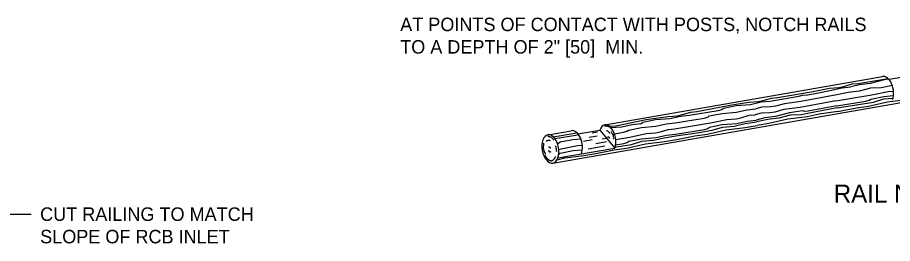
# Model space of a CAD drawing. Extents: x 49991 to 50288, y 49919 to 50011.
# Drawn here: x 50008.695 to 50012.585, y 49991.075 to 49992.081 of the extents above; entities that cross this region are included whole.
import ezdxf

# ---------------------------------------------------------------- set-up
doc = ezdxf.new("R2010")
doc.units = 0
for name, color, linetype in [('Level 1', 7, 'Continuous'), ('Level 2', 7, 'Continuous'), ('Level 3', 7, 'Continuous')]:
    doc.layers.add(name, color=color, linetype=linetype)

msp = doc.modelspace()

# ---------------------------------------------------------------- linework, layer by layer
at = {"layer": 'Level 1'}
for p, q in [((50011.07515827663, 49991.43285974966), (50014.2479885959, 49991.986852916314)), ((50011.30581186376, 49991.60257983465), (50012.54099410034, 49991.818363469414)), ((50012.66717761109, 49991.82165266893), (50012.56974109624, 49991.80464055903)), ((50011.053831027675, 49991.55884996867), (50011.15668103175, 49991.57681846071)), ((50011.18651081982, 49991.562982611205), (50011.283456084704, 49991.5799187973)), ((50011.23718243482, 49991.548498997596), (50011.27211621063, 49991.55462696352)), ((50011.24964567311, 49991.56810730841), (50011.273417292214, 49991.57229858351)), ((50011.283456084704, 49991.5799187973), (50011.35046357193, 49991.49992771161)), ((50011.21075119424, 49991.53070873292), (50011.24926361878, 49991.537436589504)), ((50011.26666973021, 49991.52050762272), (50011.31321730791, 49991.52864027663)), ((50011.29437823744, 49991.54051945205), (50011.313618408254, 49991.543912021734)), ((50011.09761781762, 49991.45575595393), (50011.35046357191, 49991.49992771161)), ((50011.2327173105, 49991.4963478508), (50011.305634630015, 49991.509151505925))]:
    msp.add_line(p, q, dxfattribs=at)
for points in [[(50012.07324422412, 49991.72466370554), (50012.23268566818, 49991.75096155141), (50012.30517618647, 49991.766056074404), (50012.346365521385, 49991.76918793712), (50012.36822040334, 49991.773762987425), (50012.40525061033, 49991.78517681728), (50012.431932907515, 49991.78725309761)], [(50012.567762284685, 49991.80683238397), (50012.547524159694, 49991.803948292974), (50012.485090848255, 49991.78719284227), (50012.438105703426, 49991.781454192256), (50012.39918382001, 49991.77178213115)], [(50012.431932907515, 49991.78725309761), (50012.565337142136, 49991.80928998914)], [(50012.040441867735, 49991.709103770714), (50012.16913199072, 49991.730356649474), (50012.18463403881, 49991.73466474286), (50012.208500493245, 49991.7364012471), (50012.24928202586, 49991.74384660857), (50012.313071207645, 49991.75714233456), (50012.35922247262, 49991.76767329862), (50012.39918382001, 49991.77178213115)], [(50012.33357019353, 49991.710384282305), (50012.493007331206, 49991.73672338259), (50012.56559667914, 49991.75186992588), (50012.58947367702, 49991.75365337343)], [(50012.584284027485, 49991.77780037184), (50012.53496525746, 49991.768648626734), (50012.48659007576, 49991.76603863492), (50012.43616170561, 49991.752934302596), (50012.38743401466, 49991.74690949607), (50012.336721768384, 49991.736924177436)], [(50011.6816977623, 49991.646446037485), (50011.81040635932, 49991.66772169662), (50011.82591056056, 49991.67200916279), (50011.83314928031, 49991.6773730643), (50011.88988445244, 49991.68898798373), (50011.95435203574, 49991.69444550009), (50012.00054455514, 49991.70498077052), (50012.040441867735, 49991.709103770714)], [(50011.71450442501, 49991.66196471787), (50011.86181156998, 49991.690905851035), (50011.94651243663, 49991.703427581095), (50011.987662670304, 49991.70653451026), (50012.00953602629, 49991.71113234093), (50012.0464815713, 49991.72255818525), (50012.07324422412, 49991.72466370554)], [(50012.33357019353, 49991.710384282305), (50012.17461243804, 49991.68105083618), (50012.101166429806, 49991.67071508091), (50012.06148892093, 49991.659692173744), (50012.0393260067, 49991.656669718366), (50012.00073117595, 49991.6548512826), (50011.97489442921, 49991.64767112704)], [(50012.336721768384, 49991.736924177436), (50012.17778033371, 49991.707634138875), (50012.10429522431, 49991.69727345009), (50012.06464049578, 49991.686232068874), (50012.042496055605, 49991.68323239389), (50012.003845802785, 49991.68134561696), (50011.978018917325, 49991.67427075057)], [(50012.3376315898, 49991.68705784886), (50012.46628907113, 49991.70822391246), (50012.48179111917, 49991.71253200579), (50012.48902553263, 49991.71793716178), (50012.54582043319, 49991.72957916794), (50012.58948304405, 49991.73328844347)], [(50012.33896423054, 49991.67908554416), (50012.43353296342, 49991.69341947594), (50012.500426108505, 49991.70440573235), (50012.54688647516, 49991.71836783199), (50012.58754041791, 49991.72210379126)], [(50012.34176188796, 49991.663071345), (50012.42418304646, 49991.67951526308), (50012.478014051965, 49991.686990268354), (50012.56265424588, 49991.706147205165), (50012.647767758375, 49991.71657487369), (50012.70037792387, 49991.72575741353)], [(50011.61930405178, 49991.61153266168), (50011.74794646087, 49991.63284311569), (50011.76351685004, 49991.63709578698), (50011.77068722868, 49991.642515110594), (50011.827509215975, 49991.65409738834), (50011.891935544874, 49991.65955059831), (50011.938105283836, 49991.670104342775), (50011.978018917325, 49991.67427075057)], [(50012.3376315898, 49991.68705784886), (50012.209385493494, 49991.66334908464), (50012.19330863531, 49991.66215048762), (50012.18475359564, 49991.66480229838), (50012.12734172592, 49991.65647390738), (50012.0649290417, 49991.639720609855), (50012.017900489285, 49991.633998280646), (50011.978994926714, 49991.62436962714)], [(50012.33896423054, 49991.67908554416), (50012.245267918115, 49991.66058888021), (50012.17860585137, 49991.648187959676), (50012.130189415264, 49991.64557366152), (50012.079806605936, 49991.63243238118), (50012.031010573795, 49991.626462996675), (50011.98036666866, 49991.616422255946)], [(50011.355760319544, 49991.599306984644), (50011.490507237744, 49991.62758437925), (50011.58777263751, 49991.64072859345), (50011.628959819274, 49991.64388108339), (50011.65078976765, 49991.64849523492), (50011.6877645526, 49991.659840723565), (50011.71450442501, 49991.66196471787)], [(50011.46328139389, 49991.60821606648), (50011.467251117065, 49991.60933941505), (50011.47446920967, 49991.61470116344), (50011.53118590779, 49991.62629330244), (50011.59561008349, 49991.631767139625), (50011.641818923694, 49991.64234581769), (50011.6816977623, 49991.646446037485)], [(50011.6162904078, 49991.58506972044), (50011.775649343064, 49991.61135895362), (50011.84823653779, 49991.62652612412), (50011.889361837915, 49991.62967215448), (50011.911257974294, 49991.63425151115), (50011.94820782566, 49991.64563610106), (50011.97489442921, 49991.64767112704)], [(50012.34176188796, 49991.663071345), (50012.25873306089, 49991.65065097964), (50012.20546756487, 49991.63935654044), (50012.11943444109, 49991.62874946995), (50012.035786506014, 49991.60967525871), (50011.98313723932, 49991.60046778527)], [(50011.32665228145, 49991.59649789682), (50011.329036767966, 49991.59722639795), (50011.355760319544, 49991.599306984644)], [(50011.333060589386, 49991.59064016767), (50011.38114065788, 49991.59467899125), (50011.42732456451, 49991.6052967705), (50011.467251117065, 49991.60933941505)], [(50011.34866228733, 49991.56343049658), (50011.38920666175, 49991.57014412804), (50011.404713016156, 49991.574410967), (50011.411970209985, 49991.57979764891), (50011.46874233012, 49991.5914581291), (50011.53316650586, 49991.596931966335), (50011.579363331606, 49991.60742598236), (50011.61930405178, 49991.61153266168)], [(50011.62033763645, 49991.56167925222), (50011.748912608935, 49991.58283670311), (50011.76448424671, 49991.58727717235), (50011.77161121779, 49991.59271281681), (50011.82841257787, 49991.6042929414), (50011.89284751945, 49991.60966364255), (50011.939081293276, 49991.62020321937), (50011.978994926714, 49991.62436962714)], [(50011.62168013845, 49991.55381223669), (50011.71610232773, 49991.568151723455), (50011.78307888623, 49991.57893816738), (50011.829551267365, 49991.59298492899), (50011.88131964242, 49991.59784664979), (50011.92931874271, 49991.60865390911), (50011.98036666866, 49991.616422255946)], [(50011.62443654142, 49991.537793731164), (50011.70677949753, 49991.5541877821), (50011.760742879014, 49991.56159319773), (50011.84533320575, 49991.580828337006), (50011.930508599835, 49991.591262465), (50011.98313723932, 49991.60046778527)], [(50011.07650606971, 49991.55050795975), (50011.1818807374, 49991.567896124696)], [(50011.08429500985, 49991.5419259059), (50011.1779538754, 49991.55737301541), (50011.18905234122, 49991.55972009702)], [(50011.351942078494, 49991.5045846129), (50011.35751122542, 49991.50542655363), (50011.42445208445, 49991.51635523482), (50011.470905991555, 49991.530379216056), (50011.522658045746, 49991.535197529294), (50011.57063867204, 49991.54598200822), (50011.62168013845, 49991.55381223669)], [(50011.35394634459, 49991.514278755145), (50011.39030428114, 49991.52027655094), (50011.40576292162, 49991.524600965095), (50011.41302442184, 49991.52994639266), (50011.46976174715, 49991.54154068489), (50011.53420224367, 49991.54705792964), (50011.580378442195, 49991.55754979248), (50011.62033763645, 49991.56167925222)], [(50011.35432657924, 49991.53833214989), (50011.41698559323, 49991.548730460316), (50011.4896118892, 49991.56392256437), (50011.53072948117, 49991.566942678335), (50011.55261269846, 49991.571645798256), (50011.589569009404, 49991.58296850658), (50011.6162904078, 49991.58506972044)], [(50011.09570934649, 49991.52015532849), (50011.10009781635, 49991.521366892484), (50011.10728882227, 49991.52678836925), (50011.16408587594, 49991.5384097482), (50011.19899842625, 49991.541345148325)], [(50011.26580973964, 49991.47521079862), (50011.3481656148, 49991.49148108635), (50011.402128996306, 49991.498886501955), (50011.48668577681, 49991.51824325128), (50011.57178512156, 49991.52860688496), (50011.62443654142, 49991.537793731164)], [(50011.10139390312, 49991.47179684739), (50011.108369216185, 49991.47708580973), (50011.16521183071, 49991.488670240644), (50011.20605815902, 49991.49212602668)], [(50011.10159282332, 49991.49403532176), (50011.11231621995, 49991.49580584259), (50011.1849098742, 49991.51091113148), (50011.20598928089, 49991.512527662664)], [(50011.093971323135, 49991.44781453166), (50011.128046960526, 49991.45557565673), (50011.21326576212, 49991.46599346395), (50011.26580973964, 49991.47521079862)]]:
    msp.add_lwpolyline(points, dxfattribs=at)
for centre, start_param, end_param in [((50012.552010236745, 49991.75545298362), 3.925707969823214, 6.306125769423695), ((50011.316874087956, 49991.53968844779), 3.9315222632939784, 7.063530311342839), ((50011.06413370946, 49991.49580670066), 3.9256121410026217, 7.063370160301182), ((50011.16856108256, 49991.51405562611), 3.9254893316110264, 6.306125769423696), ((50011.06412712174, 49991.49578870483), 0.7858875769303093, 3.9259797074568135)]:
    msp.add_ellipse(centre, major_axis=(-0.011049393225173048, 0.06292576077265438), ratio=0.5774931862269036, start_param=start_param, end_param=end_param, dxfattribs=at)
for points in [[(50011.32489066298, 49991.5929985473), (50011.322799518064, 49991.59505312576), (50011.31675475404, 49991.59702863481), (50011.313380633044, 49991.59799009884), (50011.309090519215, 49991.597938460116), (50011.305137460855, 49991.597254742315)], [(50011.31377223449, 49991.57765860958), (50011.314900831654, 49991.57723426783), (50011.31970671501, 49991.57494176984), (50011.32303967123, 49991.57157803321), (50011.32590840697, 49991.56866628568), (50011.32681256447, 49991.564798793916)], [(50011.34604103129, 49991.53880178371), (50011.34596407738, 49991.538939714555), (50011.34562925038, 49991.54714128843), (50011.3448470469, 49991.55143854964), (50011.344066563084, 49991.557716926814), (50011.33845944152, 49991.56488855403), (50011.33580188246, 49991.57097099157), (50011.33429204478, 49991.573649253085)], [(50011.03399555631, 49991.52136682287), (50011.033950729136, 49991.5190242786), (50011.03391480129, 49991.51785542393), (50011.033815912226, 49991.51669158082), (50011.0333444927, 49991.51308200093), (50011.0328380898, 49991.509478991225), (50011.032522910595, 49991.507906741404), (50011.03212706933, 49991.50634376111), (50011.03179227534, 49991.50477461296), (50011.03169205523, 49991.50398290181), (50011.03166648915, 49991.50358441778), (50011.03166023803, 49991.50318385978), (50011.031832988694, 49991.50175771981), (50011.03222079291, 49991.50036278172), (50011.0326728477, 49991.49897556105), (50011.0328758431, 49991.49827750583), (50011.03303834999, 49991.49757257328), (50011.03351549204, 49991.49497398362), (50011.03399780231, 49991.49237632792), (50011.0348418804, 49991.48835394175), (50011.035344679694, 49991.48635999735), (50011.035628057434, 49991.485369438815), (50011.03593724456, 49991.484383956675), (50011.03707273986, 49991.481789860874), (50011.03856534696, 49991.479382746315), (50011.04301372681, 49991.472924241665)], [(50011.04474557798, 49991.53024868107), (50011.045729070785, 49991.53094620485), (50011.050319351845, 49991.53364460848), (50011.05497253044, 49991.5345228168), (50011.05899129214, 49991.53526945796), (50011.06270198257, 49991.53385320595)], [(50011.0534452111, 49991.552552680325), (50011.057203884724, 49991.55190243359), (50011.06195662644, 49991.55091806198), (50011.06468269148, 49991.54997235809), (50011.067729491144, 49991.548351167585), (50011.06977076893, 49991.54637479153), (50011.071798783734, 49991.54412595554), (50011.07490337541, 49991.54155160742), (50011.07590231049, 49991.54057157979), (50011.07727275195, 49991.53862943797), (50011.0786274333, 49991.53603924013), (50011.078957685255, 49991.535072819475)], [(50011.318616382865, 49991.549610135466), (50011.31881062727, 49991.54977805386), (50011.31891154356, 49991.54986121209), (50011.31896301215, 49991.549902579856), (50011.31901517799, 49991.54994380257), (50011.31917018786, 49991.55005168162), (50011.31933120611, 49991.55013858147), (50011.31966833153, 49991.550255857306), (50011.32038238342, 49991.55030920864), (50011.32111035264, 49991.55020647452), (50011.321464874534, 49991.55012864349), (50011.32180525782, 49991.5500502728), (50011.32203356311, 49991.54999658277), (50011.32226045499, 49991.54993603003), (50011.32270750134, 49991.54978124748), (50011.323141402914, 49991.549559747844), (50011.32335186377, 49991.549415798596), (50011.323455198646, 49991.549334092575), (50011.32355716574, 49991.549245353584), (50011.323817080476, 49991.54899474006), (50011.324052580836, 49991.5487374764), (50011.324441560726, 49991.54819890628), (50011.32470655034, 49991.54762145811), (50011.324787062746, 49991.54731559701), (50011.32482999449, 49991.546996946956), (50011.32487013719, 49991.546242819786), (50011.32488388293, 49991.5454921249), (50011.324874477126, 49991.54474303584), (50011.32484516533, 49991.54399372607), (50011.32482312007, 49991.543536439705), (50011.32480140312, 49991.54307919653), (50011.324776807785, 49991.542622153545), (50011.32474612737, 49991.542165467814)], [(50011.05707632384, 49991.50441172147), (50011.0571061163, 49991.504435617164), (50011.057158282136, 49991.5044768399), (50011.057313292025, 49991.50458471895), (50011.057474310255, 49991.5046716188), (50011.057811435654, 49991.50478889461), (50011.05798632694, 49991.50482244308), (50011.0581641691, 49991.504843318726), (50011.05852548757, 49991.50484224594), (50011.05871047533, 49991.50482421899), (50011.058892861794, 49991.50480205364), (50011.05907355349, 49991.50477430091), (50011.059253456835, 49991.50473951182), (50011.05960797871, 49991.50466168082), (50011.059948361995, 49991.50458331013), (50011.06017666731, 49991.5045296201), (50011.06040355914, 49991.50446906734), (50011.06085060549, 49991.50431428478), (50011.061284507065, 49991.50409278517), (50011.061494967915, 49991.5039488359), (50011.0615983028, 49991.503867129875), (50011.06170026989, 49991.503778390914), (50011.06196018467, 49991.503527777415), (50011.06219568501, 49991.50327051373), (50011.062401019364, 49991.503010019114), (50011.062495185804, 49991.502873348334), (50011.06258466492, 49991.50273194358), (50011.06273337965, 49991.50245019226), (50011.06284965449, 49991.50215449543), (50011.06293016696, 49991.50184863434), (50011.06297309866, 49991.50152998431), (50011.063013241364, 49991.500775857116), (50011.0630269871, 49991.500025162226), (50011.06301758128, 49991.49927607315), (50011.06298826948, 49991.4985267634), (50011.06296622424, 49991.498069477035), (50011.06294450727, 49991.497612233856), (50011.062932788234, 49991.49738376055)], [(50011.06588441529, 49991.48338071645), (50011.06575481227, 49991.48315906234), (50011.06568616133, 49991.48304776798), (50011.06565081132, 49991.482991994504), (50011.06561475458, 49991.48293613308), (50011.06550289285, 49991.48278397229), (50011.065378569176, 49991.48264972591), (50011.065097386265, 49991.4824298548), (50011.06443883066, 49991.48214874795), (50011.06371669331, 49991.482010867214), (50011.06335603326, 49991.48197002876), (50011.06300857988, 49991.48193426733), (50011.06277516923, 49991.48191134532), (50011.062540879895, 49991.48189537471), (50011.062067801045, 49991.4818974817), (50011.06158561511, 49991.481966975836), (50011.061339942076, 49991.4820352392), (50011.06121575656, 49991.48207919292), (50011.06109059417, 49991.48213024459), (50011.06076366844, 49991.482283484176), (50011.06045770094, 49991.48245090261), (50011.059915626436, 49991.48283498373), (50011.059478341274, 49991.483295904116), (50011.05930336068, 49991.48355937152), (50011.05915981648, 49991.48384707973), (50011.058878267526, 49991.48454782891), (50011.05862280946, 49991.48525385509), (50011.05838978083, 49991.48596583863), (50011.058175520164, 49991.486684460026), (50011.05804869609, 49991.487124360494), (50011.05792157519, 49991.4875641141), (50011.05779724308, 49991.48800460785), (50011.057678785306, 49991.488446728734)], [(50011.091779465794, 49991.48475852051), (50011.0920931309, 49991.48762025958), (50011.09139070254, 49991.49062808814), (50011.09044324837, 49991.4979084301), (50011.090299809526, 49991.4998373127), (50011.089890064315, 49991.50543728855), (50011.08754996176, 49991.509255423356)], [(50011.04000434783, 49991.46871425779), (50011.04256036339, 49991.4632050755), (50011.04310413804, 49991.46209796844), (50011.04368271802, 49991.46100915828), (50011.044287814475, 49991.45993279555), (50011.0449111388, 49991.45886303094), (50011.04579684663, 49991.4574545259), (50011.04676538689, 49991.45610686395), (50011.04782471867, 49991.45482560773), (50011.04839091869, 49991.45421162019), (50011.04898280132, 49991.453616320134), (50011.05131943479, 49991.451577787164), (50011.053789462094, 49991.449718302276), (50011.05535814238, 49991.4486072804), (50011.056942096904, 49991.447534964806), (50011.05855107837, 49991.44649642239), (50011.06019483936, 49991.44548672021), (50011.061179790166, 49991.44494052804), (50011.0621866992, 49991.44446764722), (50011.063235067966, 49991.44405480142), (50011.06378089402, 49991.443866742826), (50011.064344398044, 49991.44368871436), (50011.06531614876, 49991.44344468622), (50011.06628056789, 49991.44330550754), (50011.06723428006, 49991.44327541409), (50011.06770606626, 49991.44330259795), (50011.06817390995, 49991.44335864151), (50011.069423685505, 49991.44361377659), (50011.0706596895, 49991.4439902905), (50011.07247322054, 49991.44475539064), (50011.07306358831, 49991.44505761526), (50011.074134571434, 49991.44564409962), (50011.07516612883, 49991.44625709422), (50011.07710733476, 49991.44766918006), (50011.07792148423, 49991.44842821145), (50011.0787161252, 49991.449203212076), (50011.08026355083, 49991.45079280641), (50011.08091286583, 49991.45148226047), (50011.08157564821, 49991.45216508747), (50011.082875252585, 49991.453549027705), (50011.08402963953, 49991.455020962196), (50011.08490608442, 49991.45665722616), (50011.08588160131, 49991.45919416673), (50011.08679668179, 49991.46168289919)]]:
    msp.add_spline(points, degree=3, dxfattribs=at)
at = {"layer": 'Level 3'}
msp.add_line((50008.6530989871, 49991.205643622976), (50008.756098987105, 49991.205643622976), dxfattribs=at)

# ---------------------------------------------------------------- texts
at = {"layer": 'Level 2'}
for s, height, p in [('AT POINTS OF CONTACT WITH POSTS, NOTCH RAILS', 0.05999999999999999, (50010.39661811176, 49992.020241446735)), ('TO A DEPTH OF 2" [50]  MIN. ', 0.05999999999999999, (50010.39661811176, 49991.920241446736)), ('RAIL NOTCHING', 0.08000000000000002, (50012.32400377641, 49991.257199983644)), ('CUT RAILING TO MATCH', 0.05999999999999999, (50008.796098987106, 49991.17564362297)), ('SLOPE OF RCB INLET', 0.05999999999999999, (50008.796098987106, 49991.07564362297))]:
    msp.add_text(s, height=height, dxfattribs=at).set_placement(p)

doc.saveas('drawing.dxf')
